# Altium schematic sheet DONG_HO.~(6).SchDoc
size A
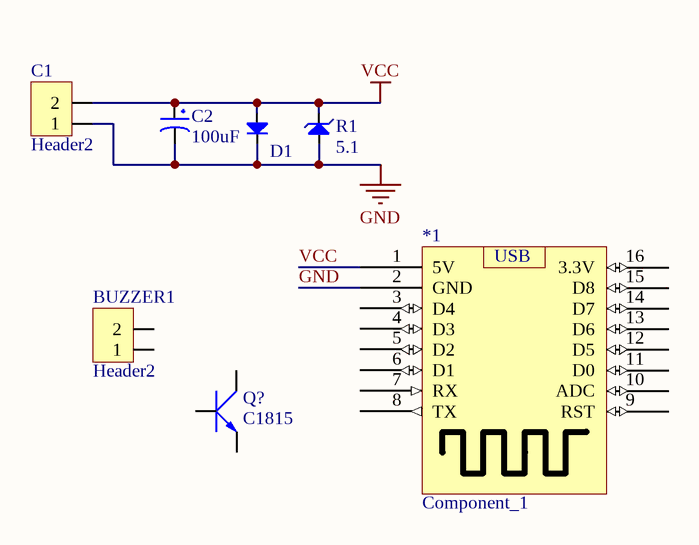
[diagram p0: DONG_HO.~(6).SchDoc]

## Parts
*1  Component_1  [ESP WEMOS MINI]
BUZZER1  Header2  [Header2]
C1  Header2  [Header2]
C2  100uF  [CP1/2.5]
D1  Diode  [DIO-1A-SMALL]  (value not drawn)
Q?  C1815  [QTO-92]
R1  5.1  [DIO-1A-ZEN]

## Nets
GND: *1.2(GND) C1.1 C2.2 D1.2(K) R1.1(A)
VCC: *1.1(5V) C1.2 C2.1 D1.1(A) R1.2(K)

Not connected (* = marked no-connect by the designer): *1 3(D4) 4(D3) 5(D2) 6(D1) 7(RX) 8(TX) 9(RST) 10(ADC) 11(D0) 12(D5) 13(D6) 14(D7) 15(D8) 16(3.3V); BUZZER1 1 2; Q? 1(E) 2(C) 3(B)

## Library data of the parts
BUZZER1 C1 = Header2: Header IDC, 2 x 1 Pin Vertical 2.54mm Pitch (Non-Boxed, Male); Manufacturer: W¨¹rth Elektronik eiSos GmbH; partNo: 613002143121; ComponentLink1 Description: Manufacturer; ComponentLink2 Description: Datasheet; NoPins: 02
C2 = CP2: C 47uF/50V , 220uF/16V; Value: 47uF/16 - 50V; Description 1: 470uF/6,3V - 330uF/10V - 220uF/16V; Description 2: 100uF/25V - 35V - 47uF/50V - 22uF/100V; Description 3: 33uF => 47uF/63V - 1uF => 4,7uF/160V; Description 4: 1uF => 2,2uF/250V - 1uF/350V
D1 = Diode: Default Diode; Code - JEDEC: DO-214-AB; Value: 1N5007
Q? = C1815: NPN 600mW, ECB
R1 = DIODE Zener: Zenner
